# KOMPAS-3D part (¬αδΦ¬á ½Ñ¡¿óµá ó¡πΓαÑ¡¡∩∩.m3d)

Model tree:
1. Эскиз:1
2. Операция выдавливания:1
     Расстояние 1 = 1; Расстояние 2 = 1
3. Эскиз:3
4. Операция выдавливания:5
     Расстояние 1 = 1; Расстояние 2 = 1
5. Скругление:3
     Радиус = 0.5
6. Скругление:4
     Радиус = 0.5
7. Массив по концентрической сетке:5  (with: Операция выдавливания:5, Скругление:3, Скругление:4)  (labels: Экземпляр ( 1, 1 ); Экземпляр ( 1, 2 ); Экземпляр ( 1, 3 ); Экземпляр ( 1, 4 ))
     N 2 = 10; Шаг 2 = 360
8. Скругление:6
     Радиус = 0.1
9. Скругление:7
     Радиус = 0.1
10. Эскиз:4
11. Операция выдавливания:6
     Расстояние 1 = 0.5; Угол 1 = 30; Расстояние 2 = 1
12. Скругление:9
     Радиус = 0.1
13. Скругление:10
     Радиус = 2
14. Эскиз:7
15. Операция выдавливания:9
     Расстояние 1 = 0.2; Расстояние 2 = 1
16. Эскиз:8
17. Операция выдавливания:10
     Расстояние 1 = 0.5; Расстояние 2 = 1
18. Массив по концентрической сетке:6  (with: Операция выдавливания:9, Операция выдавливания:10)  (labels: Экземпляр ( 1, 1 ); Экземпляр ( 1, 2 ); Экземпляр ( 1, 3 ); Экземпляр ( 1, 4 ))
     N 2 = 10; Шаг 2 = 360
19. Эскиз:10
20. Отверстие:1
21. Скругление:12
     Радиус = 0.1

Referenced files in C:\Program Files\ASCON\KOMPAS-3D V13 Home\Sys\: holelib.lfr
Referenced files in C:\Program Files\ASCON\KOMPAS-3D V12\Sys\: holelib.lfr
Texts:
  крышка ленивца наружняя
  Сплав АЛ8  ГОСТ 1583-93
  Отверстие 02
  (вариант 2)
  Номер 1
  Номер 2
